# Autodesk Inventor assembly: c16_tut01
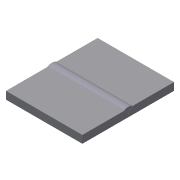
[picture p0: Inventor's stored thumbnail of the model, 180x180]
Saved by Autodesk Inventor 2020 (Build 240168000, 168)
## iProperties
Created: 2010-05
Part Number: c16_tut01
Document SubType Name: Weldment
Designer: CADSoft
Weld Material: Welded Aluminum-6061
Author: CADSoft
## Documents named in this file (2)
- D:\Autodesk Inventor_2020\Resources\Resources\Inventor_2020_tut\Inventor_2020_tut\c16_Inv_2020_tut\c16_Inv_tut_2020\c16_tut01\c16_tut01.iam
- D:\Autodesk Inventor_2020\Resources\Resources\Inventor_2020_tut\Inventor_2020_tut\c16_Inv_2020_tut\c16_Inv_tut_2020\c16_tut01\Plate.ipt
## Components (2 placed, 1 different names)
1. Plate:1 — Mate:1, Flush:1, Flush:2
2. Plate:2 — Mate:1, Flush:1, Flush:2
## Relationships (3: Flush 2, Mate 1)
- Mate:1: Plate:1 ↔ Plate:2
- Flush:1: Plate:1 ↔ Plate:2
- Flush:2: Plate:1 ↔ Plate:2
